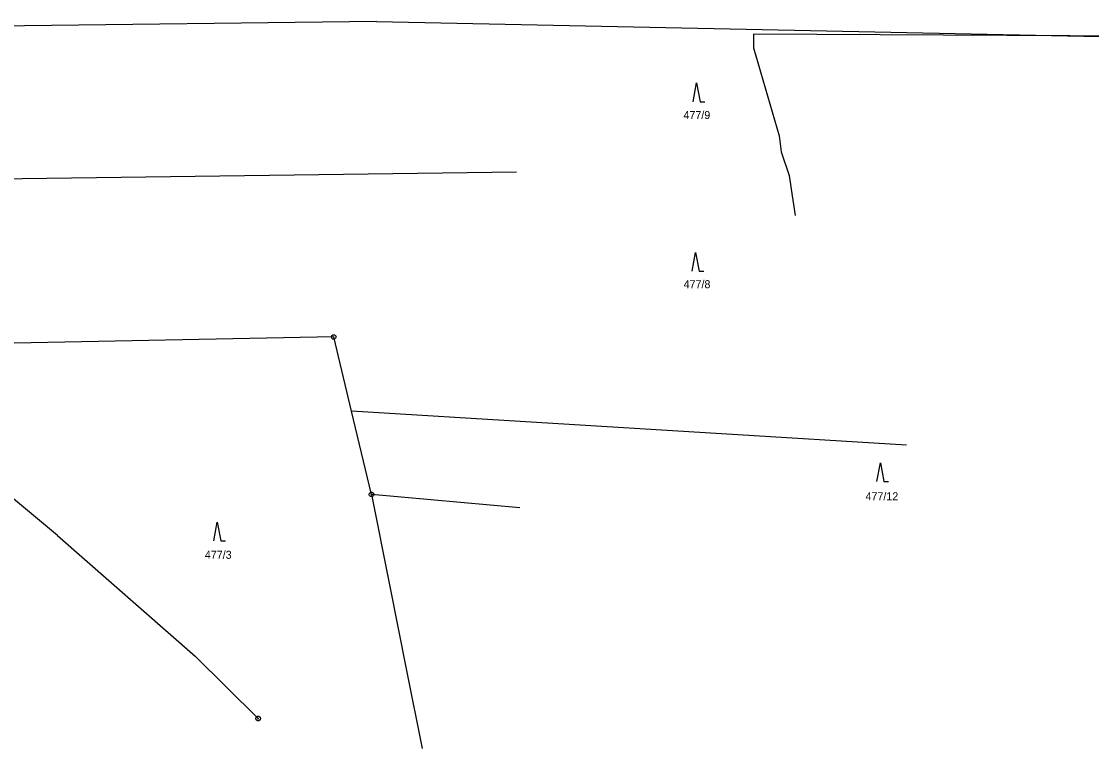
# Model space of a CAD drawing. Extents: x -759060 to -757386, y -1172273 to -1170948.
# Drawn here: x -758856.1 to -758628.9, y -1172272.5 to -1172118.1 of the extents above; entities that cross this region are included whole.
import ezdxf

# ---------------------------------------------------------------- set-up
doc = ezdxf.new("R2010")
doc.units = 0
for name, color, linetype in [('Vrstva 1', 7, 'Continuous'), ('Vrstva 11', 7, 'Continuous'), ('Vrstva 2', 7, 'Continuous'), ('Vrstva 3', 7, 'Continuous'), ('Vrstva 8', 7, 'Continuous')]:
    doc.layers.add(name, color=color, linetype=linetype)

msp = doc.modelspace()

# ---------------------------------------------------------------- linework, layer by layer
at = {"layer": 'Vrstva 1'}
for p, q in [((-758780.68, -1172118.1), (-758942.58, -1172120.16)), ((-758780.68, -1172118.1), (-758585.98, -1172122.15)), ((-758917.42, -1172152.29), (-758750.99, -1172150.02)), ((-758750.99, -1172150.02), (-758750.99, -1172150.02)), ((-758789.77, -1172185.12), (-758887.36, -1172187.02)), ((-758786, -1172200.86), (-758789.77, -1172185.12)), ((-758668.14, -1172208.08), (-758786, -1172200.86)), ((-758781.76, -1172218.56), (-758786, -1172200.86)), ((-758848.42, -1172227.25), (-758879.01, -1172201.85)), ((-758668.14, -1172208.08), (-758668.14, -1172208.08)), ((-758750.23, -1172221.43), (-758781.76, -1172218.56)), ((-758781.76, -1172218.56), (-758777.95, -1172237.73)), ((-758750.23, -1172221.43), (-758750.23, -1172221.43)), ((-758848.42, -1172227.25), (-758819.19, -1172252.9)), ((-758777.95, -1172237.73), (-758774.33, -1172255.92)), ((-758777.95, -1172237.73), (-758777.95, -1172237.73)), ((-758819.19, -1172252.9), (-758805.81, -1172266.15)), ((-758774.33, -1172255.92), (-758771.03, -1172272.53)), ((-758774.33, -1172255.92), (-758774.33, -1172255.92)), ((-758805.81, -1172266.15), (-758805.81, -1172266.15)), ((-758771.03, -1172272.53), (-758771.03, -1172272.53)), ((-758771.03, -1172272.53), (-758771.03, -1172272.53))]:
    msp.add_line(p, q, dxfattribs=at)
at = {"layer": 'Vrstva 11'}
for p, q in [((-758633.43, -1172121.16), (-758700.66, -1172120.78)), ((-758700.66, -1172120.78), (-758700.66, -1172123.74)), ((-758587.44, -1172121.42), (-758633.43, -1172121.16)), ((-758700.66, -1172123.74), (-758695.16, -1172142.38)), ((-758695.16, -1172142.38), (-758694.74, -1172145.77)), ((-758694.74, -1172145.77), (-758693.05, -1172150.86)), ((-758693.05, -1172150.86), (-758692.62, -1172153.7)), ((-758692.62, -1172153.7), (-758691.78, -1172159.33))]:
    msp.add_line(p, q, dxfattribs=at)
at = {"layer": 'Vrstva 3'}
for points in [[(-758713.48, -1172135.18), (-758712.73, -1172131.18), (-758711.98, -1172135.18), (-758710.98, -1172135.18)], [(-758713.7, -1172171.17), (-758712.95, -1172167.17), (-758712.2, -1172171.17), (-758711.2, -1172171.17)], [(-758674.46, -1172215.81), (-758673.71, -1172211.81), (-758672.96, -1172215.81), (-758671.96, -1172215.81)], [(-758815.25, -1172228.42), (-758814.5, -1172224.42), (-758813.75, -1172228.42), (-758812.75, -1172228.42)]]:
    msp.add_lwpolyline(points, dxfattribs=at)
at = {"layer": 'Vrstva 8'}
for p, q in [((-758789.89, -1172185.12), (-758789.65, -1172185.12)), ((-758781.88, -1172218.56), (-758781.64, -1172218.56)), ((-758805.93, -1172266.15), (-758805.69, -1172266.15))]:
    msp.add_line(p, q, dxfattribs=at)
for points in [[(-758789.62, -1172184.64), (-758789.37, -1172184.82), (-758789.27, -1172185.11), (-758789.37, -1172185.4), (-758789.62, -1172185.58), (-758789.93, -1172185.58), (-758790.18, -1172185.4), (-758790.28, -1172185.11), (-758790.18, -1172184.82), (-758789.93, -1172184.64)], [(-758781.61, -1172218.08), (-758781.36, -1172218.26), (-758781.26, -1172218.55), (-758781.36, -1172218.84), (-758781.61, -1172219.02), (-758781.92, -1172219.02), (-758782.17, -1172218.84), (-758782.27, -1172218.55), (-758782.17, -1172218.26), (-758781.92, -1172218.08)], [(-758805.66, -1172265.67), (-758805.41, -1172265.85), (-758805.31, -1172266.14), (-758805.41, -1172266.43), (-758805.66, -1172266.61), (-758805.97, -1172266.61), (-758806.22, -1172266.43), (-758806.32, -1172266.14), (-758806.22, -1172265.85), (-758805.97, -1172265.67)]]:
    msp.add_lwpolyline(points, close=True, dxfattribs=at)

# ---------------------------------------------------------------- texts
at = {"layer": 'Vrstva 2'}
for s, p in [('477/9', (-758715.513, -1172138.83)), ('477/8', (-758715.483, -1172174.76)), ('477/12', (-758676.863, -1172219.8)), ('477/3', (-758817.143, -1172232.22))]:
    msp.add_text(s, height=1.7, dxfattribs=at).set_placement(p)

doc.saveas('drawing.dxf')
